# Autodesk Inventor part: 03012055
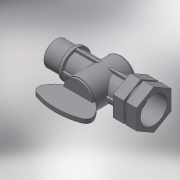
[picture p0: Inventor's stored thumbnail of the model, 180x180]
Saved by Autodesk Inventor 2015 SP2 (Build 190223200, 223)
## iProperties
Created: 2017-05
Part Number: 03012055
Material: Generic
Description: PLASSON 1/4 TURN VALVE MALE THREADED X FEMALE THREADED 1/2"X1/2"
Document SubType Name: Modeling
Designer: KIM
Density: 1 g/cm^3
Appearance: Default
Author: KIM
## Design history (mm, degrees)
derived "03012.ipt"
feature "Solid1::03012.ipt"
tag "TaggingFeature1"
body "Solid1"
other parameters: "d0" = 89, "d1" = 15, "d3" = 20.955, "d4" = 12.59228, "d15" = 20.955, "d16" = 25.146, "d17" = 18, "d19" = 0.245, "d31" = 49, "d32" = 0, "d33" = 17.96667, "d34" = 24.5, "d36" = 14.37333, "d38" = 2.45, "d45" = 49, "d46" = 52, "d47" = 45, "d48" = 4, "d49" = 0, "d50" = 29, "d51" = 2, "d52" = 0, "d63" = 18.631, "d64" = 28, "d66" = 14, "d67" = 18.2, "d68" = 26.0834, "d70" = 8.1417, "d71" = 0, "d72" = 8.1417, "d73" = 0, "d74" = 9.3155, "d75" = 1.8631, "d76" = 0, "d78" = 360 deg, "H_" = 89, "A_" = 49, "l_3" = 14, "l_2" = 15, "R_" = 20.955, "Rp_" = 18.631, "d69" = 8.1417
